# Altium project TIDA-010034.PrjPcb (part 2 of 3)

## Sheet TIDA-010034 PoE INPUT.SchDoc: PoE Input
size 431 x 279 mm; Date: Not shown in title block; ApprovedBy: Not shown in title block; CheckedBy: Not shown in title block; Author: Not shown in title block; CompanyName: Not shown in title block; DrawnBy: Surya Mishra; Engineer: Surya Mishra; Organization: Not shown in title block; Address1: Not shown in title block; Address2: Not shown in title block; Address3: Not shown in title block; Address4: Not shown in title block; DocumentNumber: 1; Revision: E1; SheetNumber: 2; SheetTotal: 9; PageSetup: Record=PageOptions¦CenterHorizontal=True¦CenterVertical=True¦PrintScale=1.00¦XCorrection=1.00¦YCorrection=1.00¦PrintKind=0¦BorderSize=5000000¦LeftOffset=0¦BottomOffset=0¦Orientation=2¦PaperLength=1000¦PaperWidth=1000¦Scale=100¦PaperSource=15¦PrintQuality=600¦MediaType=1¦DitherType=10¦PaperKind=Letter¦PrintScaleMode=1
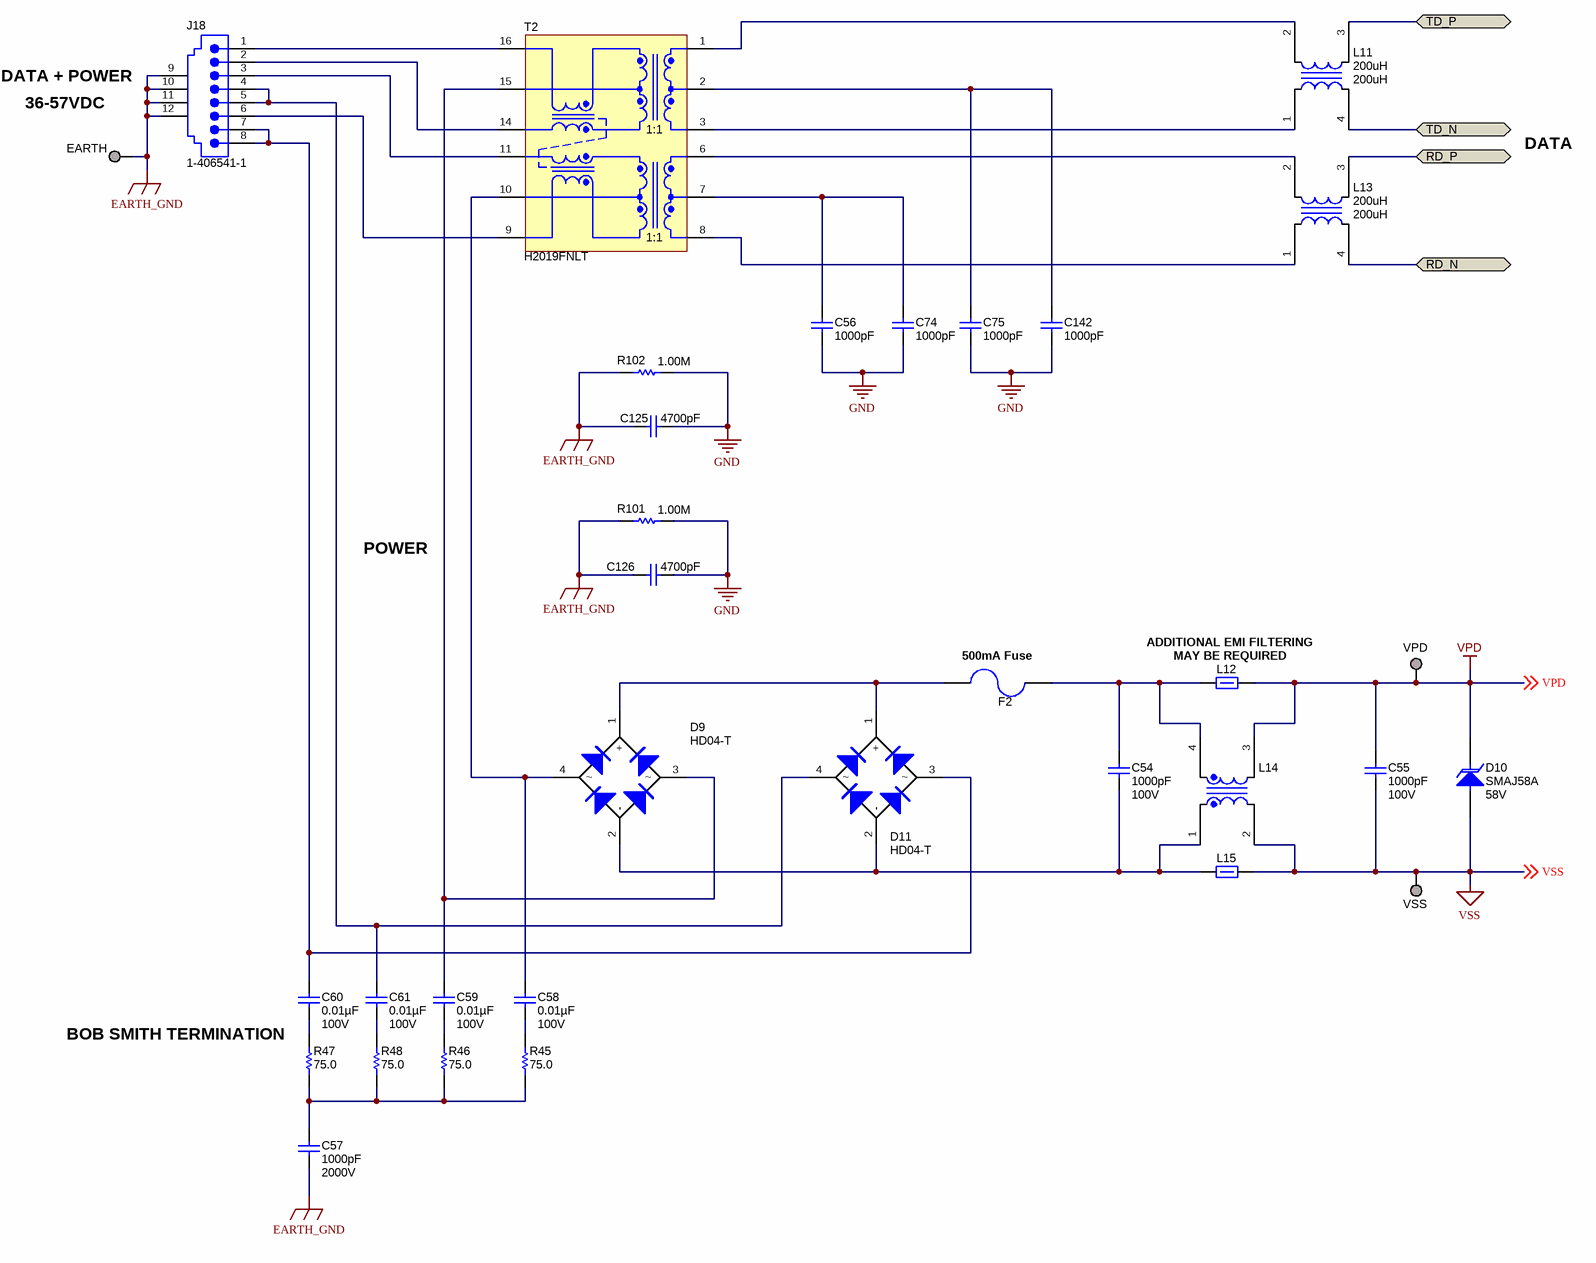
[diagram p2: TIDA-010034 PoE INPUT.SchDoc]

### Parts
C54  ValueDisplayed: 1000pF  Value2: 100V  [0603L]  (hidden comment: GRM188R72A102KA01D)
C55  ValueDisplayed: 1000pF  Value2: 100V  [0603L]  (hidden comment: GRM188R72A102KA01D)
C56  ValueDisplayed: 1000pF  [0603]  (hidden comment: GRM188R72A102KA01D)
C57  ValueDisplayed: 1000pF  Value2: 2000V  [1812]  (hidden comment: GR443QR73D102KW01L)
C58  ValueDisplayed: 0.01µF  Value2: 100V  [0603L]  (hidden comment: GRM188R72A103KA01D)
C59  ValueDisplayed: 0.01µF  Value2: 100V  [0603L]  (hidden comment: GRM188R72A103KA01D)
C60  ValueDisplayed: 0.01µF  Value2: 100V  [0603L]  (hidden comment: GRM188R72A103KA01D)
C61  ValueDisplayed: 0.01µF  Value2: 100V  [0603L]  (hidden comment: GRM188R72A103KA01D)
C74  ValueDisplayed: 1000pF  [0603]  (hidden comment: GRM188R72A102KA01D)
C75  ValueDisplayed: 1000pF  [0603]  (hidden comment: GRM188R72A102KA01D)
C125  ValueDisplayed: 4700pF  [1812_254]  (hidden comment: 1812GC472KAT1A)
C126  ValueDisplayed: 4700pF  [1812_254]  (hidden comment: 1812GC472KAT1A)
C142  ValueDisplayed: 1000pF  [0603]  (hidden comment: GRM188R72A102KA01D)
D9  HD04-T  [MiniDIP]
D10  SMAJ58A  value 58V  [SMA]
D11  HD04-T  [MiniDIP]
EARTH  TESTPOINT  [Keystone_5019]  (value not drawn)
F2  3413.0113.11  [Fuse_USF1206]  (value not drawn)
J18  1-406541-1  [TEC_1-406541-1]
L11  value 200uH  [TDK_ACT45L]  (hidden comment: ACT45L-201-2P-TL000)
L12  (no value)  [0603]
L13  value 200uH  [TDK_ACT45L]  (hidden comment: ACT45L-201-2P-TL000)
L14  DLW44SM242SK2L  [MuRata_DLW44SN]  (value not drawn)
L15  (no value)  [0603]
R45  value 75.0  [0603L]  (hidden comment: CRCW060375R0FKEA)
R46  value 75.0  [0603L]  (hidden comment: CRCW060375R0FKEA)
R47  value 75.0  [0603L]  (hidden comment: CRCW060375R0FKEA)
R48  value 75.0  [0603L]  (hidden comment: CRCW060375R0FKEA)
R101  ValueDisplayed: 1.00M  [2010]  (hidden comment: HVCB2010FKC1M00)
R102  ValueDisplayed: 1.00M  [2010]  (hidden comment: HVCB2010FKC1M00)
T2  H2019FNLT  [PULSE_H2019FNL]
VPD  TESTPOINT  [Keystone_5019]  (value not drawn)
VSS  TESTPOINT  [Keystone_5019]  (value not drawn)

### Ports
RD_N (bidir), RD_P (bidir), TD_N (bidir), TD_P (bidir)

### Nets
EARTH_GND: C57.1 C125.2 C126.2 EARTH.1 J18.9 J18.10 J18.11 J18.12 R101.1 R102.1
GND: C56.2 C74.2 C75.2 C125.1 C126.1 C142.2 R101.2 R102.2
VPD: C55.1 D10.1(K) L12.2 L14.3 VPD.1 ; off-sheet VPD
VSS: C55.2 D10.2(A) L14.2 L15.2 VSS.1 ; off-sheet VSS
RD_N: L13.4 ; port RD_N
RD_P: L13.3 ; port RD_P
TD_N: L11.4 ; port TD_N
TD_P: L11.3 ; port TD_P
NetC54_1: C54.1 F2.1 L12.1 L14.4
NetC54_2: C54.2 D9.2(-) D11.2(-) L14.1 L15.1
NetC56_1: C56.1 C74.1 T2.7(RCT)
NetC57_2: C57.2 R45.1 R46.1 R47.1 R48.1
NetC58_1: C58.1 D9.4 T2.10(RXCT)
NetC58_2: C58.2 R45.2
NetC59_1: C59.1 D9.3 T2.15(TXCT)
NetC59_2: C59.2 R46.2
NetC60_1: C60.1 D11.3 J18.7 J18.8
NetC60_2: C60.2 R47.2
NetC61_1: C61.1 D11.4 J18.4 J18.5
NetC61_2: C61.2 R48.2
NetC75_1: C75.1 C142.1 T2.2(TCT)
NetD9_1: D9.1(+) D11.1(+) F2.2
NetJ18_1: J18.1 T2.16(TX+)
NetJ18_2: J18.2 T2.14(TX-)
NetJ18_3: J18.3 T2.11(RX+)
NetJ18_6: J18.6 T2.9(RX-)
NetL11_1: L11.1 T2.3(TD-)
NetL11_2: L11.2 T2.1(TD+)
NetL13_1: L13.1 T2.8(RD-)
NetL13_2: L13.2 T2.6(RD+)

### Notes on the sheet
- DATA + POWER
- (near EARTH) 36-57VDC
- DATA
- POWER
- (near F2) 500mA Fuse
- (near L12) ADDITIONAL EMI FILTERING
- (near L12) MAY BE REQUIRED
- BOB SMITH TERMINATION

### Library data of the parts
C54 C55 = GRM188R72A102KA01D: CAP, CERM, 1000 pF, 100 V, +/- 10%, X7R, 0603; Manufacturer: MuRata; Polarized: N; CompType: Capacitor; Value: 1000pF; U/M: EA; Cap_F: 0.000000001; Tolerance_%: 10; Value1: Unknown; VDC_V: 100; TaMin_C: -55; TaMax_C: 125; Cap_Case: 0603; SizeArea_mm2: 1.28; SizeAreaWB_mm2: 4.68; SizeX_mm: 1.6; SizeY_mm: 0.8; SizeZ_mm: 1; AEC Category: Q200
C56 C74 C75 C142 = GRM188R72A102KA01D: CAP, CERM, 1000 pF, 100 V,+/- 10%, X7R, 0603; Manufacturer: MuRata; Polarized: N; CompType: Capacitor; Value: 1000pF; U/M: EA; Cap_F: 0.000000001; Tolerance_%: 10; VDC_V: 100; Value2: 100V; TaMin_C: -55; TaMax_C: 125; SizeArea_mm2: 1.28; SizeAreaWB_mm2: 4.68; SizeX_mm: 1.6; SizeY_mm: 0.8; SizeZ_mm: 1; AEC Category: Q200; Green_Lifecycle: Active; Green_REACh: Passed
C57 = GR443QR73D102KW01L: CAP, CERM, 1000 pF, 2000 V, +/- 10%, X7R, 1812; Manufacturer: MuRata; Polarized: N; CompType: Capacitor; Value: 1000pF; U/M: EA; Cap_F: 0.000000001; Tolerance_%: 10; Value1: Unknown; VDC_V: 2000; TaMin_C: -55; TaMax_C: 125; SizeArea_mm2: 14.4; SizeAreaWB_mm2: 23.1; SizeX_mm: 4.5; SizeY_mm: 3.2; SizeZ_mm: 1.35; AEC Category: Q200
C58-C61 = GRM188R72A103KA01D: CAP, CERM, 0.01 µF, 100 V, +/- 10%, X7R, 0603; Manufacturer: MuRata; Polarized: N; CompType: Capacitor; Value: 0.01uF; U/M: EA; Cap_F: 0.00000001; Tolerance_%: 10; Value1: Unknown; VDC_V: 100; TaMin_C: -55; TaMax_C: 125; Cap_Case: 0603; SizeArea_mm2: 1.28; SizeAreaWB_mm2: 4.68; SizeX_mm: 1.6; SizeY_mm: 0.8; SizeZ_mm: 1; AEC Category: Q200
C125 = CMP-0009295-2: CAP, CERM, 4700 pF, 2000 V, +/- 10%, X7R, 1812; Manufacturer: AVX; Polarized: N; Value: 4700pF; U/M: EA; Cap_F: 4.7nF; Value1: Unknown; VDC_V: 2kV; Value2: 2000V; TaMin_C: -55°C; TaMax_C: 125°C; Cap_Case: 1812; AEC Category: Q200; SizeArea_mm2: 14.4; SizeAreaWB_mm2: 23.1; SizeX_mm: 4.5; SizeY_mm: 3.2; SizeZ_mm: 2.54
C126 = CMP-0009295-2: CAP, CERM, 4700 pF, 2000 V, +/- 10%, X7R, 1812; Manufacturer: AVX; Polarized: N; CompType: Capacitor; Value: 4700pF; U/M: EA; Cap_F: 4.7nF; Value1: Unknown; VDC_V: 2kV; Value2: 2000V; TaMin_C: -55°C; TaMax_C: 125°C; Cap_Case: 1812; AEC Category: Q200; SizeArea_mm2: 14.4; SizeAreaWB_mm2: 23.1; SizeX_mm: 4.5; SizeY_mm: 3.2; SizeZ_mm: 2.54
D9 D11 = HD04-T: Diode, Switching-Bridge, 400V, 0.8A, MiniDIP; Manufacturer: Diodes Inc.; U/M: EA; Vf_V: 1; Value2: 1V; Io_A: 0.8; Vr_V: 400; TJmax_C: 150
D10 = SMAJ58A: Diode, TVS, Uni, 58 V, 400 W, SMA; Manufacturer: Diodes Inc.; U/M: EA; Power_W: 400; Vr_V: 58; Value1: 400W
EARTH VPD VSS = 5019: Test Point, Miniature, SMT; Manufacturer: Keystone; CompType: Test Point Loop; U/M: EA
F2 = CMP-0084010-1: Fuse, 0.5 A, 125VAC/VDC, SMD; Manufacturer: Schurter; Fuse Technology: Board Mount; VAC_V: 125V; SizeAreaWB_mm2: 10.92; Rtyp_Ohm: 0.315; SizeArea_mm2: 5.12; Fuse Speed: Fast; MeltingTyp: 0.01; Irating_A: 500mA; TaMax_C: 90°C; SizeZ_mm: 0.6; TaMin_C: -55°C; SizeY_mm: 1.6; SizeX_mm: 3.2
J18 = 1-406541-1: RJ-45, No LED, tab up, R/A, TH; Manufacturer: TE Connectivity; SymbolCreator: x0208326; CompType: Connector; ContactFinish: Gold
L11 L13 = CMP-0013189-2: Coupled inductor, 200 uH,  A, 4.5 ohm, SMD; Manufacturer: TDK; SizeAreaWB_mm2: 23.1; DCR_ohm: 4.5; SizeZ_mm: 2.95; SizeY_mm: 3.2; SizeArea_mm2: 14.4; Ind_H: 200µH
L12 L15 = CMP-0003355-2: Ferrite Bead, 330 ohm @ 100 MHz, 1.5 A, 0603; Manufacturer: MuRata; PartNumber: BLM18SG331TN1D; ZTyp@100MHz_Ohm: 330; SizeAreaWB_mm2: 4.68; DCR_ohm: 0.07; Value1: 0.07 ohm; Value: 330 ohm; Imax_A: 1.5A; SizeZ_mm: 1; SizeX_mm: 1.6; SizeY_mm: 0.8; SizeArea_mm2: 1.28
L14 = CMP-0084019-1: Coupled inductor, 0.105 ohm, SMD; Manufacturer: MuRata; SizeZ_mm: 1.5; SizeX_mm: 4.2; AEC Category: Q200; SizeArea_mm2: 17.64; AEC Qualified: N; SizeAreaWB_mm2: 27.04; DCR_ohm: 0.105
R45-R48 = CRCW060375R0FKEA: RES, 75.0 ohm, 1%, 0.1W, 0603; Manufacturer: Vishay-Dale; CompType: Resistor; Res_ohm: 75; Value_Code: 75R0; Tolerance_%: 1; Power_W: 0.1; TempCo: 100 ppm/C; EIA_Code: E96; U/M: EA
R101 R102 = CMP-0016535-2: RES, 1.00 M, 1%, 1 W, 2010; Manufacturer: Stackpole Electronics Inc; Power_W: 1W; TempCo: 50 ppm/C; Value_Code: 1M00; U/M: EA; Value: 1.00Meg; EIA_Code: E96; Res_ohm: 1M; SizeX_mm: 5; SizeY_mm: 2.5; SizeZ_mm: 1.66; SizeArea_mm2: 12.5; AEC Qualified: N; VDC_V: 2kV; AEC Category: Q200
T2 = H2019FNLT: Transformer, 350uH, SMT; Manufacturer: Pulse Engineering; SymbolCreator: x0208325; DCR_Ohm: 0.65; U/M: EA

## Sheet TIDA-010034 USB INPUT.SchDoc: USB Input for MSP430
size 431 x 279 mm; Date: Not shown in title block; ApprovedBy: Not shown in title block; CheckedBy: Not shown in title block; Author: Not shown in title block; CompanyName: Not shown in title block; DrawnBy: Surya Mishra; Engineer: Surya Mishra; Organization: Not shown in title block; Address1: Not shown in title block; Address2: Not shown in title block; Address3: Not shown in title block; Address4: Not shown in title block; DocumentNumber: 1; Revision: E1; SheetNumber: 6; SheetTotal: 9; PageSetup: Record=PageOptions¦CenterHorizontal=True¦CenterVertical=True¦PrintScale=1.00¦XCorrection=1.00¦YCorrection=1.00¦PrintKind=0¦BorderSize=5000000¦LeftOffset=0¦BottomOffset=0¦Orientation=2¦PaperLength=1000¦PaperWidth=1000¦Scale=100¦PaperSource=15¦PrintQuality=600¦MediaType=1¦DitherType=10¦PaperKind=Letter¦PrintScaleMode=1
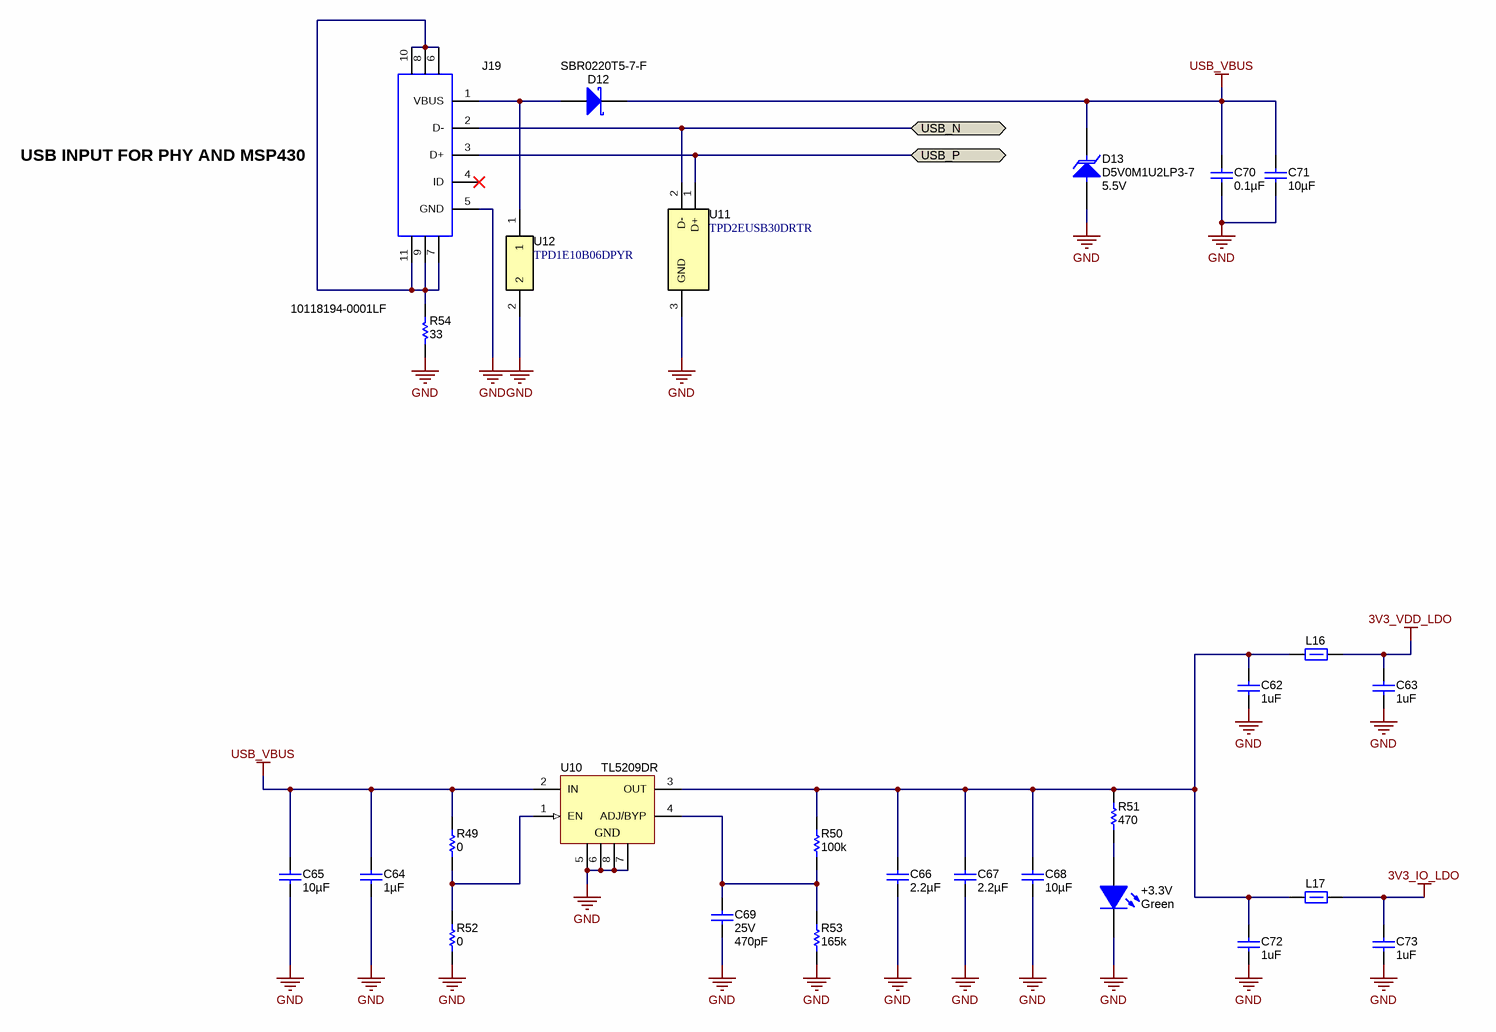
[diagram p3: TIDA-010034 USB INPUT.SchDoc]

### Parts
+3.3V  value Green  [QTLP630C_Green]  (hidden comment: QTLP630C4TR)
C62  ValueDisplayed: 1uF  [0402]  (hidden comment: GRM155R61A105KE15D)
C63  ValueDisplayed: 1uF  [0402]  (hidden comment: GRM155R61A105KE15D)
C64  ValueDisplayed: 1µF  [0603]  (hidden comment: GRM188R71C105KE15D)
C65  ValueDisplayed: 10µF  [0603]  (hidden comment: GRM188R61E106MA73D)
C66  ValueDisplayed: 2.2µF  [0603]  (hidden comment: GRM188Z71C225KE43)
C67  ValueDisplayed: 2.2µF  [0603]  (hidden comment: GRM188Z71C225KE43)
C68  ValueDisplayed: 10µF  [0603]  (hidden comment: GRM188R61E106MA73D)
C69  VDC_V: 25V  ValueDisplayed: 470pF  [0402]  (hidden comment: GRM1555C1E471JA01D)
C70  ValueDisplayed: 0.1µF  [0402]  (hidden comment: GCM155R71C104KA55D)
C71  ValueDisplayed: 10µF  [0603]  (hidden comment: GRM188R61E106MA73D)
C72  ValueDisplayed: 1uF  [0402]  (hidden comment: GRM155R61A105KE15D)
C73  ValueDisplayed: 1uF  [0402]  (hidden comment: GRM155R61A105KE15D)
D12  SBR0220T5-7-F  [SOD-523]
D13  D5V0M1U2LP3-7  value 5.5V  [X3-DFN0603-2]
J19  10118194-0001LF  [FCI_10118194-0001LF]
L16  BLM18AG102SN1D  [0603]  (value not drawn)
L17  BLM18AG102SN1D  [0603]  (value not drawn)
R49  ValueDisplayed: 0  [0402]  (hidden comment: CRCW04020000Z0ED)
R50  ValueDisplayed: 100k  [0402]  (hidden comment: CRCW0402100KDHEDP)
R51  ValueDisplayed: 470  [0402]  (hidden comment: CRCW0402470RJNED)
R52  ValueDisplayed: 0  [0402]  (hidden comment: CRCW04020000Z0ED)
R53  ValueDisplayed: 165k  [0402]  (hidden comment: CRCW0402165KFKED)
R54  ValueDisplayed: 33  [0402]  (hidden comment: CRCW040233R0JNED)
U10  TL5209DR  [D0008A_N]
U11  TPD2EUSB30DRTR  [DRT0003A]
U12  TPD1E10B06DPYR  [DPY0002A]

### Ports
USB_N (bidir), USB_P (bidir)

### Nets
3V3_IO_LDO: C73.1 L17.2
3V3_VDD_LDO: C63.1 L16.2
GND: +3.3V.2(K) C62.2 C63.2 C64.2 C65.2 C66.2 C67.2 C68.2 C69.2 C70.2 C71.2 C72.2 C73.2 D13.2(A) J19.5(GND) R52.1 R53.1 R54.2 U10.5(GND) U10.6(GND) U10.7(GND) U10.8(GND) U11.3(GND) U12.2
USB_VBUS: C64.1 C65.1 C70.1 C71.1 D12.1(K) D13.1(K) R49.2 U10.2(IN)
USB_N: J19.2(D-) U11.2(D-) ; port USB_N
USB_P: J19.3(D+) U11.1(D+) ; port USB_P
Net+3.3V_1: +3.3V.1(A) R51.1
NetC62_1: C62.1 C66.1 C67.1 C68.1 C72.1 L16.1 L17.1 R50.2 R51.2 U10.3(OUT)
NetC69_1: C69.1 R50.1 R53.2 U10.4(ADJ/BYP)
NetD12_2: D12.2(A) J19.1(VBUS) U12.1
NetJ19_6: J19.6 J19.7 J19.8 J19.9 J19.10 J19.11 R54.1
NetR49_1: R49.1 R52.2 U10.1(EN)

Not connected (* = marked no-connect by the designer): J19 4(ID)*

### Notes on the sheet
- USB INPUT FOR PHY AND MSP430

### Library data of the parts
+3.3V = CMP-0002917-1: LED, Green, SMD; Manufacturer: Everlight; Vf_V: 2.1V; Io_A: 20mA; Vr_V: 5V; Tjmax_C: 85°C; Value1: W; Angle: 140; U/M: EA
C62 C63 C72 C73 = CMP-0006563-2: CAP, CERM, 1 uF, 10 V, +/- 10%, X5R, 0402; Manufacturer: MuRata; Polarized: N; Value: 1uF; U/M: EA; Cap_F: 1µF; Value1: Unknown; VDC_V: 10V; TaMin_C: -55°C; TaMax_C: 85°C; AEC Category: Q200; SizeArea_mm2: 0.5; SizeAreaWB_mm2: 3; SizeX_mm: 1; SizeZ_mm: 0.6
C64 = GRM188R71C105KE15D: CAP, CERM, 1 µF, 16 V,+/- 10%, X7R, 0603; Manufacturer: MuRata; Polarized: N; CompType: Capacitor; Value: 1uF; U/M: EA; Cap_F: 0.000001; Tolerance_%: 10; VDC_V: 16; Value2: 16V; TaMin_C: -55; TaMax_C: 125; SizeArea_mm2: 1.28; SizeAreaWB_mm2: 4.68; SizeX_mm: 1.6; SizeY_mm: 0.8; SizeZ_mm: 1; AEC Category: Q200
C65 C68 C71 = GRM188R61E106MA73D: CAP, CERM, 10 µF, 25 V,+/- 20%, X5R, 0603; Manufacturer: MuRata; Polarized: N; CompType: Capacitor; Value: 10uF; U/M: EA; Cap_F: 0.00001; Tolerance_%: 20; VDC_V: 25; Value2: 25V; TaMin_C: -55; TaMax_C: 85; SizeArea_mm2: 1.28; SizeAreaWB_mm2: 4.68; SizeX_mm: 1.6; SizeY_mm: 0.8; SizeZ_mm: 1; AEC Category: Q200; Green_Lifecycle: Active; Green_REACh: Passed
C66 C67 = GRM188Z71C225KE43: CAP, CERM, 2.2 µF, 16 V,+/- 10%, X7R, 0603; Manufacturer: MuRata; Polarized: N; CompType: Capacitor; Value: 2.2uF; U/M: EA; Cap_F: 0.0000022; Tolerance_%: 10; VDC_V: 16; Value2: 16V; TaMin_C: -55; TaMax_C: 125; SizeArea_mm2: 1.28; SizeAreaWB_mm2: 4.68; SizeX_mm: 1.6; SizeY_mm: 0.8; SizeZ_mm: 1; AEC Category: Q200; Green_Lifecycle: Active; Green_REACh: Passed
C69 = CMP-0006389-2: CAP, CERM, 470 pF, 25 V, +/- 5%, C0G/NP0, 0402; Manufacturer: MuRata; TaMin_C: -55°C; Polarized: N; SizeAreaWB_mm2: 3; Value1: Unknown; U/M: EA; Value: 470pF; TaMax_C: 125°C; SizeZ_mm: 0.6; SizeX_mm: 1; SizeY_mm: 0.5; CompType: Capacitor; AEC Category: Q200
C70 = GCM155R71C104KA55D: CAP, CERM, 0.1 µF, 16 V,+/- 10%, X7R, 0402; Manufacturer: MuRata; Polarized: N; CompType: Capacitor; Value: 0.1uF; U/M: EA; Cap_F: 0.0000001; Tolerance_%: 10; VDC_V: 16; Value2: 16V; TaMin_C: -55; TaMax_C: 125; SizeArea_mm2: 0.5; SizeAreaWB_mm2: 3; SizeX_mm: 1; SizeZ_mm: 0.6; AEC Category: Q200; Green_Lifecycle: Active; Green_REACh: Passed
D12 = SBR0220T5-7-F: Diode, Schottky, 20 V, 0.2 A, SOD-523; Manufacturer: Diodes Inc.; U/M: EA; Vf_V: 0.47; Value: 20V; Value1: 0.2A; Value2: 0.47V; Io_A: 0.2; Vr_V: 20; SizeAreaWB_mm2: 5.13; SizeArea_mm2: 1.53; SizeX_mm: 1.7; SizeY_mm: 0.9; SizeZ_mm: 0.65; AEC Category: Q101; Green_Lifecycle: Not Set; Green_REACh: Incomplete
D13 = D5V0M1U2LP3-7: Diode, TVS, Uni, 5.5 V, 11 Vc, 2-XFDFN; Manufacturer: Diodes Inc.; U/M: EA; Power_W: 0.25; Vr_V: 5.5; Value1: 0.25W; RJA_CperW: 500; AEC Category: Q101; AEC Qualified: N
J19 = 10118194-0001LF: Receptacle, USB 2.0, Micro-USB Type B, R/A, SMT; Manufacturer: FCI; SymbolCreator: a0411947; Pitch_mm: 0.65; Gender: Female; Row_Count: 1; ContactFinish: Gold; Current_A: 1.8; Voltage_V: 100; Cert_UL: Y
L16 L17 = CMP-0003343-2: Ferrite Bead, 1000 ohm @ 100 MHz, 0.4 A, 0603; Manufacturer: MuRata; ZTyp@100MHz_Ohm: 1k; SizeAreaWB_mm2: 4.68; DCR_ohm: 5d; Value1: 0.5 ohm; Imax_A: 4dA; SizeZ_mm: 1; SizeX_mm: 1.6; SizeY_mm: 0.8; Value2: 0.4A; SizeArea_mm2: 1.28
R49 R52 = CRCW04020000Z0ED: RES, 0, 5%, 0.063 W, 0402; Manufacturer: Vishay-Dale; CompType: Resistor; Value: 0; Value_Code: 0000; Tolerance_%: 5; Power_W: 0.063; Value2: 0.063W; VDC_V: 50; TempCo: 200 ppm/C; SizeArea_mm2: 0.5; SizeX_mm: 1; SizeZ_mm: 0.6; EIA_Code: E24; U/M: EA; AEC Category: Q200; Green_Lifecycle: Active; Green_REACh: Passed
R50 = CMP-0026768-2: RES, 100 k, 0.5%, 0.063 W, AEC-Q200 Grade 0, 0402; Manufacturer: Vishay-Dale; Power_W: 63mW; TempCo: 50 ppm/C; Value: 100k; EIA_Code: E192; SizeX_mm: 1; SizeY_mm: 0.5; SizeZ_mm: 0.6; Value2: 0.063W; CompType: Resistor; AEC Qualified: Y; VDC_V: 50V; AEC Category: Q200; AEC Grade: 0
R51 = CMP-0026934-3: RES, 470, 5%, 0.063 W, AEC-Q200 Grade 0, 0402; Manufacturer: Vishay-Dale; Power_W: 63mW; TempCo: 200 ppm/C; Value_Code: 470R; Value: 470; EIA_Code: E24; SizeX_mm: 1; SizeY_mm: 0.5; SizeZ_mm: 0.6; Value2: 0.063W; CompType: Resistor; AEC Qualified: Y; VDC_V: 50V; AEC Category: Q200; AEC Grade: 0
R53 = CMP-0026036-3: RES, 165 k, 1%, 0.063 W, AEC-Q200 Grade 0, 0402; Manufacturer: Vishay-Dale; Power_W: 63mW; TempCo: 100 ppm/C; Value: 165k; EIA_Code: E96; SizeX_mm: 1; SizeY_mm: 0.5; SizeZ_mm: 0.6; Value2: 0.063W; AEC Qualified: Y; VDC_V: 50V; AEC Category: Q200; AEC Grade: 0
R54 = CMP-0026908-3: RES, 33, 5%, 0.063 W, AEC-Q200 Grade 0, 0402; Manufacturer: Vishay-Dale; Value: 33; Value_Code: 33R0; Power_W: 63mW; Value2: 0.063W; VDC_V: 50V; TempCo: 200 ppm/C; EIA_Code: E24; AEC Category: Q200; AEC Qualified: Y; AEC Grade: 0; SizeArea_mm2: 0.5; SizeX_mm: 1; SizeZ_mm: 0.6
U10 = CMP-0036447-1: Single Output Low Noise LDO, 500 mA, Adjustable 1.3 to 6.5 V Output, 2.5 to 16 V Input, 8-pin SOIC (D), -40 to 125 degC, Green (RoHS & no Sb/Br); Manufacturer: Texas Instruments; Iq(Typ)(mA): 8; Accuracy(%): 2; Vdo(Typ)(mV): 500; Iout(Max)(A): 0.5; Vin(Max)(V): 16; Vout Adj(Min)(V): 2.5; Vout Adj(Max)(V): 6.5; SubFamily: Single Channel LDO; Rating: Catalog
U11 = TPD2EUSB30DRTR: ESD Solution for Super-Speed (6 Gbps) USB 3.0 Interface, 2 Channels, -40 to +85 degC, 3-pin SOT (DRT), Green (Rohs & No Sb/Br); Manufacturer: Texas Instruments; Alternate PartNumber: Equivalent; 1394 / Firewire: TRUE; Breakdown Voltage(Min)(V): 9; Differential Capacitance(pF): 0.01; IEC 61000-4-2 Air-Gap(+/- kV): 8; IO Capacitance(Typ)(pF): 0.7; IO Leakage Current(nA): 10
U12 = TPD1E10B06DPYR: ESD in 0402 Package with 10 pF Capacitance and 6 V Breakdown, 1 Channel, -40 to +125 degC, 2-pin X2SON (DPY), Green (RoHS & no Sb/Br); Manufacturer: Texas Instruments; Alternate PartNumber: Equivalent; Breakdown Voltage(Min)(V): 6; Eco-Plan: TBD; IEC 61000-4-2 Air-Gap(+/- kV): 30; IO Capacitance(Typ)(pF): 10; SubFamily: ESD Solution

## Sheet TIDA-010034 Block Diagram.SchDoc: TIDA-010034 Power tree block diagram
size 431 x 279 mm; Date: Not shown in title block; ApprovedBy: Not shown in title block; CheckedBy: Not shown in title block; Author: Not shown in title block; CompanyName: Not shown in title block; DrawnBy: Surya Mishra; Engineer: Surya Mishra; Organization: Not shown in title block; Address1: Not shown in title block; Address2: Not shown in title block; Address3: Not shown in title block; Address4: Not shown in title block; DocumentNumber: 1; Revision: E1; SheetNumber: 1; SheetTotal: 9; PageSetup: Record=PageOptions¦CenterHorizontal=True¦CenterVertical=True¦PrintScale=1.00¦XCorrection=1.00¦YCorrection=1.00¦PrintKind=0¦BorderSize=5000000¦LeftOffset=0¦BottomOffset=0¦Orientation=2¦PaperLength=1000¦PaperWidth=1000¦Scale=100¦PaperSource=15¦PrintQuality=600¦MediaType=1¦DitherType=10¦PaperKind=Letter¦PrintScaleMode=1

## Sheet TIDA-010034 TPS23755 PD FRONT-END.SchDoc: TPS23755 based PD Front-end and 12V Adapter
size 431 x 279 mm; Date: Not shown in title block; ApprovedBy: Not shown in title block; CheckedBy: Not shown in title block; Author: Not shown in title block; CompanyName: Not shown in title block; DrawnBy: Surya Mishra; Engineer: Surya Mishra; Organization: Not shown in title block; Address1: Not shown in title block; Address2: Not shown in title block; Address3: Not shown in title block; Address4: Not shown in title block; DocumentNumber: 1; Revision: E1; SheetNumber: 3; SheetTotal: 9; PageSetup: Record=PageOptions¦CenterHorizontal=True¦CenterVertical=True¦PrintScale=1.00¦XCorrection=1.00¦YCorrection=1.00¦PrintKind=0¦BorderSize=5000000¦LeftOffset=0¦BottomOffset=0¦Orientation=2¦PaperLength=1000¦PaperWidth=1000¦Scale=100¦PaperSource=15¦PrintQuality=600¦MediaType=1¦DitherType=10¦PaperKind=Letter¦PrintScaleMode=1
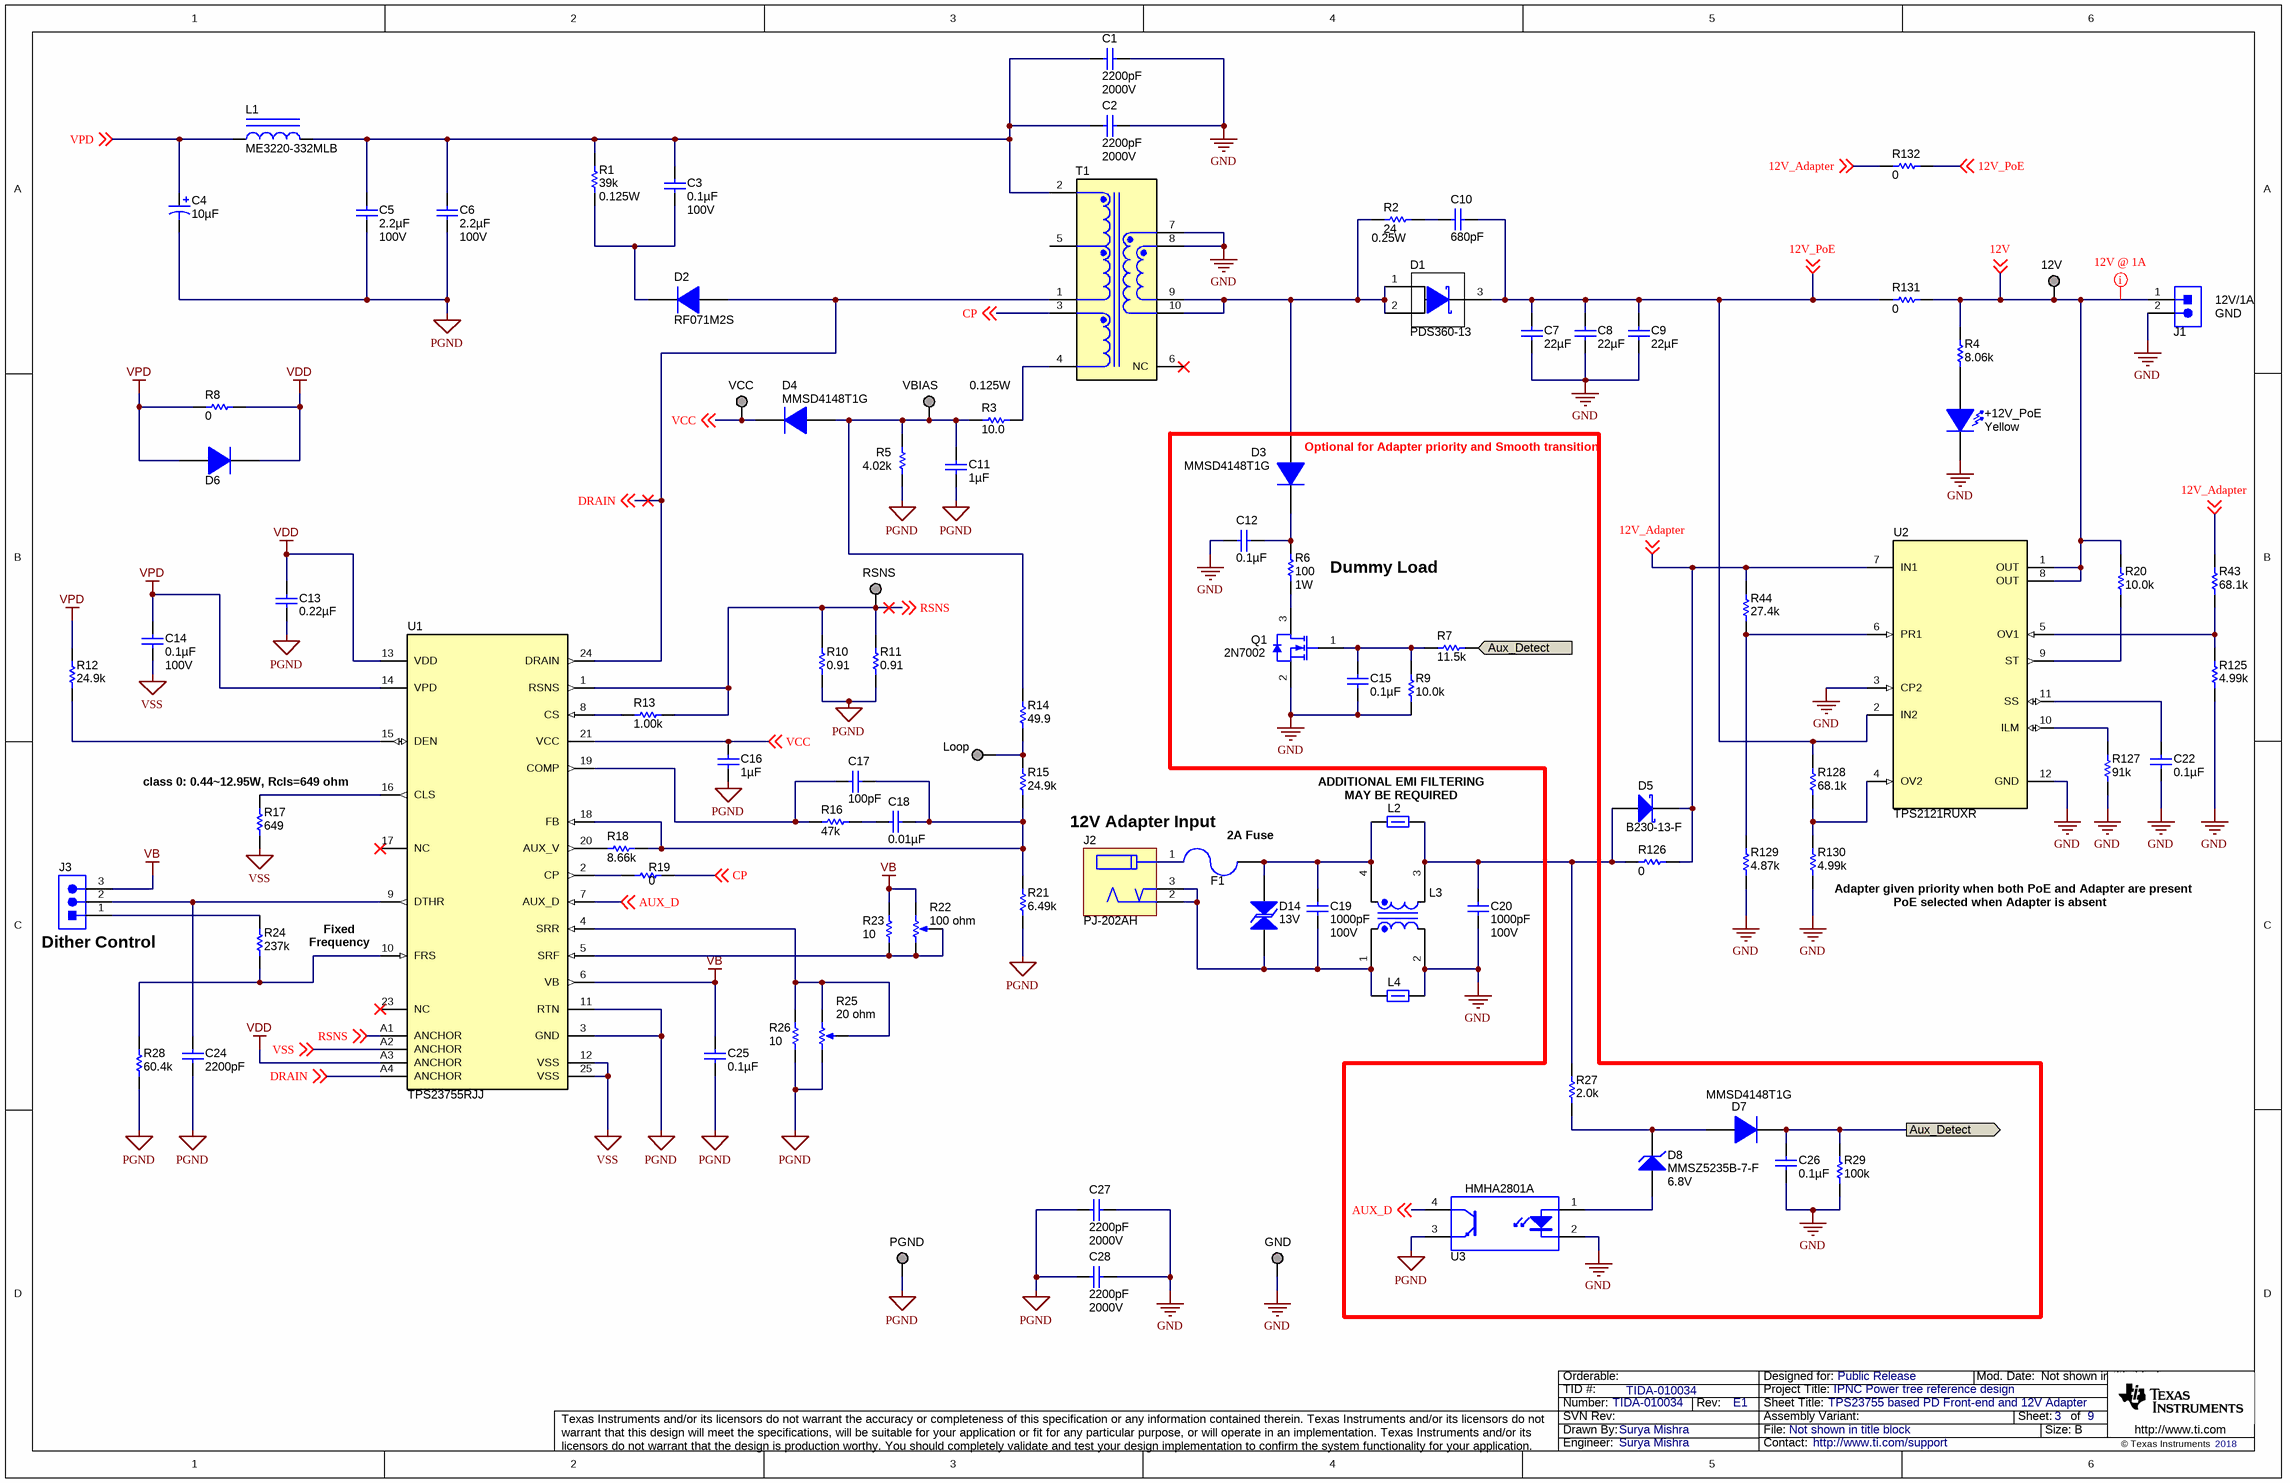
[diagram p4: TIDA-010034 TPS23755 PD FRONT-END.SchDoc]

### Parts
(Parts that share a designator on the sheet are numbered #1, #2 ... from top to bottom, then left to right.)
12V  TESTPOINT  [Keystone_5019]  (value not drawn)
+12V_PoE  value Yellow  [WL-SMCW_YELLOW]  (hidden comment: 150060YS75000)
C1  ValueDisplayed: 2200pF  Value2: 2000V  [1812]  (hidden comment: C4532X7R3D222K130KA)
C2  ValueDisplayed: 2200pF  Value2: 2000V  [1812]  (hidden comment: C4532X7R3D222K130KA)
C3  ValueDisplayed: 0.1µF  Value2: 100V  [0805_HV]  (hidden comment: C2012X7R2A104K125AA)
C4  ValueDisplayed: 10µF  [SM_RADIAL_E]  (hidden comment: EEE-2AA100UP)
C5  ValueDisplayed: 2.2µF  Value2: 100V  [1210_270L]  (hidden comment: GRM32ER72A225KA35L)
C6  ValueDisplayed: 2.2µF  Value2: 100V  [1210_270L]  (hidden comment: GRM32ER72A225KA35L)
C7  ValueDisplayed: 22µF  [1210_270]  (hidden comment: GRM32ER71E226KE15L)
C8  ValueDisplayed: 22µF  [1210_270]  (hidden comment: GRM32ER71E226KE15L)
C9  ValueDisplayed: 22µF  [1210_270]  (hidden comment: GRM32ER71E226KE15L)
C10  ValueDisplayed: 680pF  [0603]  (hidden comment: 06031C681KAT2A)
C11  ValueDisplayed: 1µF  [0805_HV]  (hidden comment: GRM21BR71H105KA12L)
C12  ValueDisplayed: 0.1µF  [0603]  (hidden comment: 06035C104KAT2A)
C13  ValueDisplayed: 0.22µF  [0805_HV]  (hidden comment: GRM21AR72A224KAC5L)
C14  ValueDisplayed: 0.1µF  Value2: 100V  [0805_HV]  (hidden comment: C2012X7R2A104K125AA)
C15  ValueDisplayed: 0.1µF  [0603]  (hidden comment: 06035C104KAT2A)
C16  ValueDisplayed: 1µF  [0805_HV]  (hidden comment: GRM21BR71H105KA12L)
C17  ValueDisplayed: 100pF  [0402L]  (hidden comment: 885012005061)
C18  ValueDisplayed: 0.01µF  [0603L]  (hidden comment: 06031C103MAT2A)
C19  ValueDisplayed: 1000pF  Value2: 100V  [0603]  (hidden comment: GRM188R72A102KA01D)
C20  ValueDisplayed: 1000pF  Value2: 100V  [0603]  (hidden comment: GRM188R72A102KA01D)
C22  ValueDisplayed: 0.1µF  [0603L]  (hidden comment: C1608X7R1E104K080AA)
C24  ValueDisplayed: 2200pF  [0603L]  (hidden comment: GRM188R71H222KA01D)
C25  ValueDisplayed: 0.1µF  [0603L]  (hidden comment: C1608X7R1E104K080AA)
C26  ValueDisplayed: 0.1µF  [0603L]  (hidden comment: 06035C104KAT2A)
C27  ValueDisplayed: 2200pF  Value2: 2000V  [1812]  (hidden comment: C4532X7R3D222K130KA)
C28  ValueDisplayed: 2200pF  Value2: 2000V  [1812]  (hidden comment: C4532X7R3D222K130KA)
D1  PDS360-13  [PowerDI5]
D2  RF071M2S  [SOD-123]
D3  MMSD4148T1G  [SOD-123]
D4  MMSD4148T1G  [SOD-123]
D5  B230-13-F  [SMB]
D6  MMSD4148T1G  [SOD-123]  (value not drawn)
D7  MMSD4148T1G  [SOD-123]
D8  MMSZ5235B-7-F  value 6.8V  [SOD-123]
D14  value 13V  [SMA]  (hidden comment: SMAJ13CA)
F1  3413.0112.24  [Fuse_USF1206]  (value not drawn)
GND#19  TESTPOINT  [Keystone_5019]  (value not drawn)
J1  ED555/2DS  [TERM_BLK_ED555-2DS]  (value not drawn)
J2  PJ-202AH  [CONN_CUI-PJ-202AH]
J3  TSW-103-07-G-S  [TSW-103-07-X-S]  (value not drawn)
L1  ME3220-332MLB  [ME3220]
L2  (no value)  [0603]
L3  DLW5BTM142TQ2L  [DLW5BT_TQ2]  (value not drawn)
L4  (no value)  [0603]
Loop  TESTPOINT  [Keystone_5019]  (value not drawn)
PGND  TESTPOINT  [Keystone_5019]  (value not drawn)
Q1  2N7002  [SOT-23]
R1  value 39k  Value2: 0.125W  [0805_HV]  (hidden comment: CRCW080539K0JNEA)
R2  ValueDisplayed: 24  Value2: 0.25W  [1206]  (hidden comment: CRCW120624R0JNEA)
R3  Value2: 0.125W  ValueDisplayed: 10.0  [0805L]  (hidden comment: RC0805FR-0710RL)
R4  ValueDisplayed: 8.06k  [0603]  (hidden comment: CRCW06038K06FKEA)
R5  ValueDisplayed: 4.02k  [0603L]  (hidden comment: CRCW06034K02FKEA)
R6  ValueDisplayed: 100  Value2: 1W  [2512]  (hidden comment: CRCW2512100RJNEG)
R7  ValueDisplayed: 11.5k  [0603]  (hidden comment: CRCW060311K5FKEA)
R8  ValueDisplayed: 0  [0603]  (hidden comment: MCT06030Z0000ZP500)
R9  ValueDisplayed: 10.0k  [0603]  (hidden comment: CRCW060310K0FKEA)
R10  ValueDisplayed: 0.91  [0805L]  (hidden comment: CRM0805-FX-R910ELF)
R11  ValueDisplayed: 0.91  [0805L]  (hidden comment: CRM0805-FX-R910ELF)
R12  ValueDisplayed: 24.9k  [0402L]  (hidden comment: CRCW040224K9FKED)
R13  ValueDisplayed: 1.00k  [0402L]  (hidden comment: ERJ-2RKF1001X)
R14  ValueDisplayed: 49.9  [0402L]  (hidden comment: RMCF0402FT49R9)
R15  ValueDisplayed: 24.9k  [0402L]  (hidden comment: CRCW040224K9FKED)
R16  ValueDisplayed: 47k  [0402L]  (hidden comment: CRCW040247K0JNED)
R17  ValueDisplayed: 649  [0603]  (hidden comment: CRCW0603649RFKEA)
R18  ValueDisplayed: 8.66k  [0402L]  (hidden comment: CRCW04028K66FKED)
R19  ValueDisplayed: 0  [0402L]  (hidden comment: RC0402JR-070RL)
R20  ValueDisplayed: 10.0k  [0603]  (hidden comment: CRCW060310K0FKEA)
R21  ValueDisplayed: 6.49k  [0402L]  (hidden comment: CRCW04026K49FKED)
R22  value 100 ohm  [Bourns_3314J-1]  (hidden comment: 3314J-1-101E)
R23  ValueDisplayed: 10  [0402L]  (hidden comment: CRCW040210R0JNED)
R24  ValueDisplayed: 237k  [0402L]  (hidden comment: CRCW0402237KFKED)
R25  value 20 ohm  [Bourns_3314J-1]  (hidden comment: 3314J-1-200E)
R26  ValueDisplayed: 10  [0402L]  (hidden comment: CRCW040210R0JNED)
R27  ValueDisplayed: 2.0k  [0603L]  (hidden comment: CRCW06032K00JNEA)
R28  ValueDisplayed: 60.4k  [0402L]  (hidden comment: CRCW040260K4FKED)
R29  ValueDisplayed: 100k  [0603L]  (hidden comment: RC0603FR-07100KL)
R43  ValueDisplayed: 68.1k  [0402]  (hidden comment: CRCW040268K1FKED)
R44  ValueDisplayed: 27.4k  [0402]  (hidden comment: CRCW040227K4FKED)
R125  ValueDisplayed: 4.99k  [0402]  (hidden comment: CRCW04024K99FKED)
R126  ValueDisplayed: 0  [1206]  (hidden comment: CRCW12060000Z0EA)
R127  ValueDisplayed: 91k  [0603]  (hidden comment: CRCW060391K0JNEA)
R128  ValueDisplayed: 68.1k  [0402]  (hidden comment: CRCW040268K1FKED)
R129  ValueDisplayed: 4.87k  [0402]  (hidden comment: CRCW04024K87FKED)
R130  ValueDisplayed: 4.99k  [0402]  (hidden comment: CRCW04024K99FKED)
R131  ValueDisplayed: 0  [1206]  (hidden comment: CRCW12060000Z0EA)
R132  ValueDisplayed: 0  [1206]  (hidden comment: CRCW12060000Z0EA)
RSNS  TESTPOINT  [Keystone_5019]  (value not drawn)
T1  LDT0950-50  [Linkcom_LDT0937-50]  (value not drawn)
U1  TPS23755RJJ  [RJJ0023B]
U2  TPS2121RUXR  [RUX0012A]
U3  HMHA2801A  [MFP04A]
VBIAS  TESTPOINT  [Keystone_5019]  (value not drawn)
VCC  TESTPOINT  [Keystone_5019]  (value not drawn)

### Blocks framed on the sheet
Dummy Load: C12 C15 C26 D3 D7 D8 Q1 R6 R7 R9 R27 R29 U3

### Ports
Aux_Detect (in), Aux_Detect (out)

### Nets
GND: +12V_PoE.1(K) C1.2 C2.2 C7.2 C8.2 C9.2 C12.1 C15.2 C20.2 C22.2 C26.2 C27.2 C28.2 GND#19.1 J1.2 L3.2 L4.2 Q1.2(S) R9.1 R29.1 R125.1 R127.1 R129.1 R130.1 T1.7 T1.8 U2.3(CP2) U2.12(GND) U3.2(K)
PGND: C4.2(-) C5.2 C6.2 C11.2 C13.2 C16.2 C24.2 C25.2 C27.1 C28.1 PGND.1 R5.1 R10.1 R11.1 R21.1 R25.1(CCW) R26.2 R28.1 U1.3(GND) U1.11(RTN) U3.3(E)
VB: C25.1 J3.3 R22.3(CW) R23.1 U1.6(VB)
VDD: C13.1 D6.1(K) R8.1 U1.13(VDD) U1.A3(ANCHOR)
VPD: C4.1(+) C14.1 D6.2(A) L1.1 R8.2 R12.1 U1.14(VPD) ; off-sheet VPD
VSS: C14.2 R17.1 U1.12(VSS) U1.25(VSS) U1.A2(ANCHOR) ; off-sheet VSS
12V: 12V.1 J1.1 R4.2 R20.2 R131.2 U2.1(OUT) U2.8(OUT) ; off-sheet 12V
12V_Adapter: D5.1(K) R43.2 R44.2 R126.2 R132.1 U2.7(IN1) ; off-sheet 12V_Adapter
12V_PoE: C7.1 C8.1 C9.1 C10.1 D1.3(K) R128.2 R131.1 R132.2 U2.2(IN2) ; off-sheet 12V_PoE
AUX_D: U1.7(AUX_D) U3.4(C) ; off-sheet AUX_D
Aux_Detect: C26.1 D7.1(K) R7.2 R29.2 ; port Aux_Detect
CP: R19.2 T1.3 ; off-sheet CP
DRAIN: D2.2(A) T1.1 U1.24(DRAIN) U1.A4(ANCHOR) ; off-sheet DRAIN
RSNS: R10.2 R11.2 R13.2 RSNS.1 U1.1(RSNS) U1.A1(ANCHOR) ; off-sheet RSNS
VCC: C16.1 D4.1(K) U1.21(VCC) VCC.1 ; off-sheet VCC
Net+12V_PoE_2: +12V_PoE.2(A) R4.1
NetC1_1: C1.1 C2.1 C3.1 C5.1 C6.1 L1.2 R1.2 T1.2
NetC3_2: C3.2 D2.1(K) R1.1
NetC10_2: C10.2 R2.2
NetC11_1: C11.1 D4.2(A) R3.1 R5.2 R14.2 VBIAS.1
NetC12_2: C12.2 D3.1(K) R6.2
NetC15_1: C15.1 Q1.1(G) R7.1 R9.2
NetC17_1: C17.1 R16.2 U1.19(COMP)
NetC17_2: C17.2 C18.2 R15.1 R18.2 R21.2 U1.18(FB)
NetC18_1: C18.1 R16.1
NetC19_1: C19.1 D14.2 F1.1 L2.1 L3.4
NetC19_2: C19.2 D14.1 J2.2 J2.3 L3.1 L4.1
NetC20_1: C20.1 D5.2(A) L2.2 L3.3 R27.2 R126.1
NetC22_1: C22.1 U2.11(SS)
NetC24_1: C24.1 J3.2 U1.9(DTHR)
NetD1_1: D1.1(A) D1.2(A) D3.2(A) R2.1 T1.9 T1.10
NetD7_2: D7.2(A) D8.1(K) R27.1
NetD8_2: D8.2(A) U3.1(A)
NetF1_2: F1.2 J2.1
NetJ3_1: J3.1 R24.2
NetLoop_1: Loop.1 R14.1 R15.2
NetQ1_3: Q1.3(D) R6.1
NetR3_2: R3.2 T1.4
NetR12_2: R12.2 U1.15(DEN)
NetR13_1: R13.1 U1.8(CS)
NetR17_2: R17.2 U1.16(CLS)
NetR18_1: R18.1 U1.20(AUX_V)
NetR19_1: R19.1 U1.2(CP)
NetR20_1: R20.1 U2.9(ST)
NetR22_1: R22.1(CCW) R22.2(WIPER) R23.2 U1.5(SRF)
NetR24_1: R24.1 R28.2 U1.10(FRS)
NetR25_2: R25.2(WIPER) R25.3(CW) R26.1 U1.4(SRR)
NetR43_1: R43.1 R125.2 U2.5(OV1)
NetR44_1: R44.1 R129.2 U2.6(PR1)
NetR127_2: R127.2 U2.10(ILM)
NetR128_1: R128.1 R130.2 U2.4(OV2)

Not connected (* = marked no-connect by the designer): T1 5 6(NC)*; U1 17(NC)* 23(NC)*

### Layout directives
net class Undefined: 12V

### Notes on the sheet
- (near J1) 12V/1A
- (near J1) GND
- (near D3) Optional for Adapter priority and Smooth transition
- (near R17) class 0: 0.44
  2.95W, Rcls=649 ohm
- 12V Adapter Input
- (near F1) 2A Fuse
- (near L2) ADDITIONAL EMI FILTERING
- (near L2) MAY BE REQUIRED
- PoE selected when Adapter is absent
- (near R130) Adapter given priority when both PoE and Adapter are present
- (near J3) Dither Control
- Frequency
- Fixed

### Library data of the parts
12V GND#19 Loop PGND RSNS VBIAS VCC = 5019: as EARTH on sheet TIDA-010034 PoE INPUT
+12V_PoE = 150060YS75000: LED, Yellow, SMD; Manufacturer: Wurth Elektronik; Vf_V: 2; Value2: 2V; Io_A: 0.02; Value1: W; U/M: EA
C1 C2 C27 C28 = C4532X7R3D222K130KA: CAP, CERM, 2200 pF, 2000 V, +/- 10%, X7R, 1812; Manufacturer: TDK; Polarized: N; CompType: Capacitor; Value: 2200pF; U/M: EA; Cap_F: 0.0000000022; Tolerance_%: 10; Value1: Unknown; VDC_V: 2000; TaMin_C: -55; TaMax_C: 125; SizeArea_mm2: 14.4; SizeAreaWB_mm2: 23.1; SizeX_mm: 4.5; SizeY_mm: 3.2; SizeZ_mm: 1.35; AEC Category: Q200
C3 C14 = C2012X7R2A104K125AA: CAP, CERM, 0.1 µF, 100 V, +/- 10%, X7R, 0805; Manufacturer: TDK; Polarized: N; CompType: Capacitor; Value: 0.1uF; U/M: EA; Cap_F: 0.0000001; Tolerance_%: 10; ESR_ohm: 0.020726; Value1: 0.020726 ohm; VDC_V: 100; IRMS_A: 1.456; TaMin_C: -55; TaMax_C: 125; Cap_Case: 0805; SizeArea_mm2: 2.5; SizeAreaWB_mm2: 6.75; SizeX_mm: 2; SizeY_mm: 1.25; SizeZ_mm: 1.45; AEC Category: Q200
C4 = EEE-2AA100UP: CAP, AL, 10 µF, 100 V, +/- 20%, AEC-Q200 Grade 3, SMD; Manufacturer: Panasonic; Polarized: Y; CompType: Capacitor; Value: 10uF; U/M: EA; Cap_F: 0.00001; Tolerance_%: 20; Value1: Unknown; VDC_V: 100; Value2: 100V; IRMS_A: 0.05; TaMin_C: -40; TaMax_C: 85; Cap_Case: 8.0x6.0mm; SizeAreaWB_mm2: 118.45; SizeArea_mm2: 78.85; SizeX_mm: 9.5; SizeY_mm: 8.3; SizeZ_mm: 6.2; AEC Category: Q200; AEC Grade: 3
C5 C6 = GRM32ER72A225KA35L: CAP, CERM, 2.2 µF, 100 V, +/- 10%, X7R, 1210; Manufacturer: MuRata; Polarized: N; CompType: Capacitor; Value: 2.2uF; U/M: EA; Cap_F: 0.0000022; Tolerance_%: 10; ESR_ohm: 0.007; Value1: 0.007 ohm; VDC_V: 100; IRMS_A: 4.4; TaMin_C: -55; TaMax_C: 125; Cap_Case: 1210; SizeArea_mm2: 8; SizeAreaWB_mm2: 14.7; SizeX_mm: 3.2; SizeY_mm: 2.5; SizeZ_mm: 2.7; AEC Category: Q200
C7-C9 = GRM32ER71E226KE15L: CAP, CERM, 22 µF, 25 V,+/- 10%, X7R, 1210; Manufacturer: MuRata; Polarized: N; CompType: Capacitor; Value: 22uF; U/M: EA; Cap_F: 0.000022; Tolerance_%: 10; ESR_ohm: 0.002334; Value1: 0.002334 ohm; VDC_V: 25; Value2: 25V; IRMS_A: 3.832999; TaMin_C: -55; TaMax_C: 125; Cap_Case: 1210; SizeArea_mm2: 8; SizeAreaWB_mm2: 14.7; SizeX_mm: 3.2; SizeY_mm: 2.5; SizeZ_mm: 2.7; AEC Category: Q200; Green_Lifecycle: Active; Green_REACh: Passed
C10 = 06031C681KAT2A: CAP, CERM, 680 pF, 100 V, +/- 10%, X7R, 0603; Manufacturer: AVX; Polarized: N; CompType: Capacitor; Value: 680pF; U/M: EA; Cap_F: 0.00000000068; Tolerance_%: 10; ESR_ohm: 0.332; Value1: 0.332 ohm; VDC_V: 100; Value2: 100V; TaMin_C: -55; TaMax_C: 125; SizeArea_mm2: 1.28; SizeAreaWB_mm2: 4.68; SizeX_mm: 1.6; SizeY_mm: 0.8; SizeZ_mm: 1; AEC Category: Q200
C11 C16 = GRM21BR71H105KA12L: CAP, CERM, 1 µF, 50 V,+/- 10%, X7R, 0805; Manufacturer: MuRata; Polarized: N; CompType: Capacitor; Value: 1uF; U/M: EA; Cap_F: 0.000001; Tolerance_%: 10; VDC_V: 50; Value2: 50V; TaMin_C: -55; TaMax_C: 125; Cap_Case: 0805; SizeArea_mm2: 2.5; SizeAreaWB_mm2: 6.75; SizeX_mm: 2; SizeY_mm: 1.25; SizeZ_mm: 1.45; AEC Category: Q200; Green_Lifecycle: Active; Green_REACh: Passed
C12 C15 = 06035C104KAT2A: CAP, CERM, 0.1 µF, 50 V,+/- 10%, X7R, 0603; Manufacturer: AVX; Polarized: N; CompType: Capacitor; Value: 0.1uF; U/M: EA; Cap_F: 0.0000001; Tolerance_%: 10; VDC_V: 50; Value2: 50V; TaMin_C: -55; TaMax_C: 125; SizeArea_mm2: 1.28; SizeAreaWB_mm2: 4.68; SizeX_mm: 1.6; SizeY_mm: 0.8; SizeZ_mm: 1; AEC Category: Q200; Green_Lifecycle: Active; Green_REACh: Passed
C13 = GRM21AR72A224KAC5L: CAP, CERM, 0.22 µF, 100 V,+/- 10%, X7R, 0805; Manufacturer: MuRata; Polarized: N; CompType: Capacitor; Value: 0.22uF; U/M: EA; Cap_F: 0.00000022; Tolerance_%: 10; VDC_V: 100; Value2: 100V; TaMin_C: -55; TaMax_C: 125; Cap_Case: 0805; SizeArea_mm2: 2.5; SizeAreaWB_mm2: 6.75; SizeX_mm: 2; SizeY_mm: 1.25; SizeZ_mm: 1.45; AEC Category: Q200
C17 = 885012005061: CAP, CERM, 100 pF, 50 V,+/- 5%, C0G/NP0, 0402; Manufacturer: Wurth Elektronik; Polarized: N; CompType: Capacitor; Value: 100pF; U/M: EA; Cap_F: 0.0000000001; Tolerance_%: 5; VDC_V: 50; Value2: 50V; TaMin_C: -55; TaMax_C: 125; Cap_Case: 0402; SizeArea_mm2: 0.5; SizeAreaWB_mm2: 3; SizeX_mm: 1; SizeZ_mm: 0.6; AEC Category: Q200; Green_Lifecycle: Not Set; Green_REACh: Incomplete
C18 = 06031C103MAT2A: CAP, CERM, 0.01 µF, 100 V,+/- 20%, X7R, 0603; Manufacturer: AVX; Polarized: N; CompType: Capacitor; Value: 0.01uF; U/M: EA; Cap_F: 0.00000001; Tolerance_%: 20; ESR_ohm: 0.098; Value1: 0.098 ohm; VDC_V: 100; Value2: 100V; TaMin_C: -55; TaMax_C: 125; Cap_Case: 0603; SizeArea_mm2: 1.28; SizeAreaWB_mm2: 4.68; SizeX_mm: 1.6; SizeY_mm: 0.8; SizeZ_mm: 1; AEC Category: Q200; Green_Lifecycle: Active; Green_REACh: Passed
C19 C20 = GRM188R72A102KA01D: CAP, CERM, 1000 pF, 100 V, +/- 10%, X7R, 0603; Manufacturer: MuRata; Polarized: N; CompType: Capacitor; Value: 1000pF; U/M: EA; Cap_F: 0.000000001; Tolerance_%: 10; Value1: Unknown; VDC_V: 100; TaMin_C: -55; TaMax_C: 125; SizeArea_mm2: 1.28; SizeAreaWB_mm2: 4.68; SizeX_mm: 1.6; SizeY_mm: 0.8; SizeZ_mm: 1; AEC Category: Q200
C22 C25 = C1608X7R1E104K080AA: CAP, CERM, 0.1 µF, 25 V, +/- 10%, X7R, 0603; Manufacturer: TDK; Polarized: N; CompType: Capacitor; Value: 0.1uF; U/M: EA; Cap_F: 0.0000001; Tolerance_%: 10; Value1: Unknown; VDC_V: 25; Value2: 25V; TaMin_C: -55; TaMax_C: 125; Cap_Case: 0603; SizeArea_mm2: 1.28; SizeAreaWB_mm2: 4.68; SizeX_mm: 1.6; SizeY_mm: 0.8; SizeZ_mm: 1; AEC Category: Q200
C24 = GRM188R71H222KA01D: CAP, CERM, 2200 pF, 50 V, +/- 10%, X7R, 0603; Manufacturer: MuRata; Polarized: N; CompType: Capacitor; Value: 2200pF; U/M: EA; Cap_F: 0.0000000022; Tolerance_%: 10; Value1: Unknown; VDC_V: 50; Value2: 50V; TaMin_C: -55; TaMax_C: 125; Cap_Case: 0603; SizeArea_mm2: 1.28; SizeAreaWB_mm2: 4.68; SizeX_mm: 1.6; SizeY_mm: 0.8; SizeZ_mm: 1; AEC Category: Q200
C26 = 06035C104KAT2A: CAP, CERM, 0.1 µF, 50 V,+/- 10%, X7R, 0603; Manufacturer: AVX; Polarized: N; CompType: Capacitor; Value: 0.1uF; U/M: EA; Cap_F: 0.0000001; Tolerance_%: 10; VDC_V: 50; Value2: 50V; TaMin_C: -55; TaMax_C: 125; Cap_Case: 0603; SizeArea_mm2: 1.28; SizeAreaWB_mm2: 4.68; SizeX_mm: 1.6; SizeY_mm: 0.8; SizeZ_mm: 1; AEC Category: Q200; Green_Lifecycle: Active; Green_REACh: Passed
D1 = PDS360-13: Diode, Schottky, 60 V, 3 A, PowerDI5; Manufacturer: Diodes Inc.; U/M: EA; Vf_V: 0.62; Value: 60V; Value1: 3A; Value2: 0.62V; Io_A: 3; Vr_V: 60; TJmax_C: 150; SizeAreaWB_mm2: 49.56; SizeArea_mm2: 24.96; SizeX_mm: 6.4; SizeY_mm: 3.9; SizeZ_mm: 1.05; AEC Category: Q101
D2 = RF071M2S: Diode, Ultrafast, 200 V, 1 A, SOD-123; Manufacturer: Rohm; Value: 200V; U/M: EA; Vf_V: 0.85; Value1: 1A; Value2: 0.85V; Io_A: 1; Vr_V: 200; TJmax_C: 150; SizeAreaWB_mm2: 13.095; SizeArea_mm2: 6.545; SizeX_mm: 3.85; SizeY_mm: 1.7; SizeZ_mm: 1.35; AEC Category: Q101; Green_Lifecycle: Not Set; Green_REACh: Incomplete
D3 D4 D6 D7 = MMSD4148T1G: Diode, Switching, 100V, 0.2A, SOD-123; Manufacturer: ON Semiconductor; U/M: EA; Vf_V: 1; Value2: 1V; Io_A: 0.2; Vr_V: 100; TJmax_C: 150
D5 = B230-13-F: Diode, Schottky, 30 V, 2 A, SMB; Manufacturer: Diodes Inc.; U/M: EA; Vf_V: 0.5; Value: 30V; Value1: 2A; Value2: 0.5V; Io_A: 2; Vr_V: 30; TJmax_C: 150; RJC_CperW: 20; SizeAreaWB_mm2: 44.156; SizeArea_mm2: 21.336; SizeX_mm: 5.6; SizeY_mm: 3.81; SizeZ_mm: 2.6; AEC Category: Q101
D8 = MMSZ5235B-7-F: Diode, Zener, 6.8 V, 500 mW, SOD-123; Manufacturer: Diodes Inc.; SymbolCreator: a0412235; U/M: EA; Power_W: 0.5; Vz_V: 6.8; Value1: 0.5W; RJA_CperW: 350; SizeAreaWB_mm2: 13.095; SizeArea_mm2: 6.545; SizeX_mm: 3.85; SizeY_mm: 1.7; SizeZ_mm: 1.35; AEC Category: Q101; Green_Lifecycle: Active; Green_REACh: Passed
D14 = SMAJ13CA: Diode, TVS, Bi, 13 V, SMA; Manufacturer: Littelfuse; U/M: EA; Power_W: 3.3; Vr_V: 13; Value1: 3.3W; RJA_CperW: 120; SizeAreaWB_mm2: 37.3428; SizeArea_mm2: 16.3228; SizeX_mm: 5.59; SizeY_mm: 2.92; SizeZ_mm: 2.87; AEC Category: Q101
F1 = CMP-0084010-1: Fuse, 2 A, 125VAC/VDC, SMD; PartNumber: 3413.0119.11; Manufacturer: Schurter; Fuse Technology: Board Mount; VAC_V: 125V; SizeAreaWB_mm2: 10.92; Rtyp_Ohm: 0.315; SizeArea_mm2: 5.12; Fuse Speed: Fast; MeltingTyp: 0.01; Irating_A: 2A; TaMax_C: 90°C; SizeZ_mm: 0.6; TaMin_C: -55°C; SizeY_mm: 1.6; SizeX_mm: 3.2
J1 = ED555/2DS: Terminal Block, 6A, 3.5mm Pitch, 2-Pos, TH; Manufacturer: On-Shore Technology; SymbolCreator: a0412235; CompType: Connector; U/M: EA
J2 = PJ-202AH: Connector, DC Jack 2.1X5.5 mm, TH; Manufacturer: CUI Inc.; SymbolCreator: a0799628; CompType: Power Jack; Green_Lifecycle: Not Set; Green_REACh: Incomplete
J3 = TSW-103-07-G-S: Header, 100mil, 3x1, Gold, TH; Manufacturer: Samtec; SymbolCreator: a0799628; Pitch_mm: 2.54; Gender: Male; Shrouded: N; Row_Count: 1; Current_A: 6.3; Voltage_V: 550; Cert_CSA: Y; Green_Lifecycle: Active; Green_REACh: Passed
L1 = ME3220-332MLB: Inductor, Drum Core, Ferrite, 3.3 µH, 1.6 A, 0.14 ohm, SMD; Manufacturer: Coilcraft; Value: 3.3uH; ValueDisplayed: 3.3µH; Ind_H: 3.3E-6; Imax_A: 1.6; Irms: 1.6A @ 40C rise; Isat: 1.7A @ 30% inductance drop; DCR_ohm: 0.14; Value2: 1.6A; SizeAreaWB_mm2: 15.96; SizeArea_mm2: 8.96; SizeX_mm: 3.2; SizeY_mm: 2.8; SizeZ_mm: 2; AEC Category: Q200
L2 L4 = CMP-0003353-2: Ferrite Bead, 220 ohm @ 100 MHz, 2.5 A, 0603; Manufacturer: MuRata; PartNumber: BLM18SG221TN1D; ZTyp@100MHz_Ohm: 220; SizeAreaWB_mm2: 4.68; DCR_ohm: 0.04; Value1: 0.04 ohm; Value: 220 ohm; Imax_A: 2.5A; SizeZ_mm: 1; SizeX_mm: 1.6; SizeY_mm: 0.8; SizeArea_mm2: 1.28
L3 = CMP-0084018-1: Coupled inductor, 0.056 ohm, SMD; Manufacturer: MuRata; PartNumber: DLW5BTM102TQ2; AEC Category: Q200; AEC Qualified: N; DCR_ohm: 0.056
Q1 = 2N7002: MOSFET, N-CH, 60 V, 115 A, SOT-23; Manufacturer: Fairchild Semiconductor; Alternate Manufacturer: None; U/M: EA; ChType: N; Value: 60V; VdsMax_V: 60; Value1: ? ohm; Value2: ? nC; Vgs_V: 20; IdsMax_A: 115; SizeAreaWB_mm2: 14; SizeArea_mm2: 7.5; SizeX_mm: 2.5; SizeY_mm: 3; SizeZ_mm: 1.1; AEC Category: Q101
R1 = CRCW080539K0JNEA: RES, 39k ohm, 5%, 0.125W, 0805; Manufacturer: Vishay-Dale; CompType: Resistor; Res_ohm: 39000; Value_Code: 39k0; Tolerance_%: 5; Power_W: 0.125; VDC_V: 150; TempCo: 200 ppm/C; EIA_Code: E24; U/M: EA
R2 = CRCW120624R0JNEA: RES, 24, 5%, 0.25 W, 1206; Manufacturer: Vishay-Dale; CompType: Resistor; Value: 24; Value_Code: 24R0; Tolerance_%: 5; Power_W: 0.25; VDC_V: 200; TempCo: 200 ppm/C; SizeArea_mm2: 5.12; SizeX_mm: 3.2; SizeY_mm: 1.6; SizeZ_mm: 1.35; EIA_Code: E24; U/M: EA; AEC Category: Q200
R3 = RC0805FR-0710RL: RES, 10.0, 1%, 0.125 W, 0805; Manufacturer: Yageo America; CompType: Resistor; Value: 10.0; Res_ohm: 10; Value_Code: 10R0; Tolerance_%: 1; Power_W: 0.125; VDC_V: 150; TempCo: 200 ppm/C; EIA_Code: E96; U/M: EA; SizeArea_mm2: 2.5; SizeX_mm: 2; SizeY_mm: 1.25; SizeZ_mm: 1.45; AEC Category: Q200; Green_Lifecycle: Active; Green_REACh: Passed
R4 = CRCW06038K06FKEA: RES, 8.06 k, 1%, 0.1 W, 0603; Manufacturer: Vishay-Dale; CompType: Resistor; Value: 8.06k; Res_ohm: 8060; Value_Code: 8k06; Tolerance_%: 1; Power_W: 0.1; Value2: 0.1W; VDC_V: 75; TempCo: 100 ppm/C; SizeArea_mm2: 1.28; SizeX_mm: 1.6; SizeY_mm: 0.8; EIA_Code: E96; U/M: EA; AEC Category: Q200; Green_Lifecycle: Active; Green_REACh: Passed
R5 = CRCW06034K02FKEA: RES, 4.02 k, 1%, 0.1 W, 0603; Manufacturer: Vishay-Dale; CompType: Resistor; Value: 4.02k; Res_ohm: 4020; Value_Code: 4k02; Tolerance_%: 1; Power_W: 0.1; Value2: 0.1W; VDC_V: 75; TempCo: 100 ppm/C; SizeArea_mm2: 1.28; SizeX_mm: 1.6; SizeY_mm: 0.8; EIA_Code: E96; U/M: EA; AEC Category: Q200; Green_Lifecycle: Active; Green_REACh: Passed
R6 = CRCW2512100RJNEG: RES, 100, 5%, 1 W, AEC-Q200 Grade 0, 2512; Manufacturer: Vishay-Dale; CompType: Resistor; Value: 100; Value_Code: 100R; Tolerance_%: 5; Power_W: 1; VDC_V: 500; TempCo: 200 ppm/C; SizeArea_mm2: 20.16; SizeX_mm: 6.3; SizeY_mm: 3.2; SizeZ_mm: 0.71; EIA_Code: E24; U/M: EA; AEC Category: Q200; AEC Qualified: Y; AEC Grade: 0
R7 = CRCW060311K5FKEA: RES, 11.5 k, 1%, 0.1 W, 0603; Manufacturer: Vishay-Dale; CompType: Resistor; Value: 11.5k; Res_ohm: 11500; Value_Code: 11k5; Tolerance_%: 1; Power_W: 0.1; Value2: 0.1W; VDC_V: 75; TempCo: 100 ppm/C; SizeArea_mm2: 1.28; SizeX_mm: 1.6; SizeY_mm: 0.8; EIA_Code: E96; U/M: EA; AEC Category: Q200
R8 = MCT06030Z0000ZP500: RES, 0, 5%, 0.125 W, 0603; Manufacturer: Vishay/Beyschlag; CompType: Resistor; Value: 0; Value_Code: 0000; Tolerance_%: 5; Power_W: 0.125; Value2: 0.125W; TempCo: ppm/C; SizeArea_mm2: 1.28; SizeX_mm: 1.6; SizeY_mm: 0.8; SizeZ_mm: 1; EIA_Code: E24; U/M: EA; AEC Category: Q200; AEC Qualified: N; Green_Lifecycle: Active; Green_REACh: Passed
R9 = CRCW060310K0FKEA: RES, 10.0 k, 1%, 0.1 W, 0603; Manufacturer: Vishay-Dale; CompType: Resistor; Value: 10.0k; Res_ohm: 10000; Value_Code: 10k0; Tolerance_%: 1; Power_W: 0.1; Value2: 0.1W; VDC_V: 75; TempCo: 100 ppm/C; SizeArea_mm2: 1.28; SizeX_mm: 1.6; SizeY_mm: 0.8; EIA_Code: E96; U/M: EA; AEC Category: Q200
R10 R11 = CRM0805-FX-R910ELF: RES, 0.91, 1%, 0.25 W, 0805; Manufacturer: Bourns; CompType: Resistor; Value: 0.91; Value_Code: R910; Tolerance_%: 1; Power_W: 0.25; Value2: 0.25W; VDC_V: 0; TempCo: 100 ppm/C; EIA_Code: E96; U/M: EA; SizeArea_mm2: 2.5; SizeX_mm: 2; SizeY_mm: 1.25; SizeZ_mm: 1.45; AEC Category: Q200
R12 R15 = CRCW040224K9FKED: RES, 24.9 k, 1%, 0.063 W, 0402; Manufacturer: Vishay-Dale; CompType: Resistor; Value: 24.9k; Res_ohm: 24900; Value_Code: 24k9; Tolerance_%: 1; Power_W: 0.063; Value2: 0.063W; VDC_V: 50; TempCo: 100 ppm/C; SizeArea_mm2: 0.5; SizeZ_mm: 0.6; EIA_Code: E96; U/M: EA; AEC Category: Q200
R13 = ERJ-2RKF1001X: RES, 1.00 k, 1%, 0.1 W, 0402; Manufacturer: Panasonic; CompType: Resistor; Value: 1.00k; Res_ohm: 1000; Value_Code: 1k00; Tolerance_%: 1; Power_W: 0.1; Value2: 0.1W; VDC_V: 50; TempCo: 100 ppm/C; SizeArea_mm2: 0.5; SizeZ_mm: 0.6; EIA_Code: E96; U/M: EA; AEC Category: Q200; Green_Lifecycle: Active; Green_REACh: Passed
R14 = RMCF0402FT49R9: RES, 49.9, 1%, 0.063 W, AEC-Q200 Grade 0, 0402; Manufacturer: Stackpole Electronics Inc; CompType: Resistor; Value: 49.9; Value_Code: 49R9; Tolerance_%: 1; Power_W: 0.063; Value2: 0.063W; VDC_V: 50; TempCo: 100 ppm/C; SizeArea_mm2: 0.5; SizeZ_mm: 0.6; EIA_Code: E96; U/M: EA; AEC Category: Q200; AEC Qualified: Y; AEC Grade: 0
R16 = CRCW040247K0JNED: RES, 47 k, 5%, 0.063 W, 0402; Manufacturer: Vishay-Dale; CompType: Resistor; Value: 47k; Res_ohm: 47000; Value_Code: 47k0; Tolerance_%: 5; Power_W: 0.063; Value2: 0.063W; VDC_V: 50; TempCo: 200 ppm/C; SizeArea_mm2: 0.5; SizeX_mm: 1; SizeZ_mm: 0.6; EIA_Code: E24; U/M: EA; AEC Category: Q200
R17 = CRCW0603649RFKEA: RES, 649, 1%, 0.1 W, 0603; Manufacturer: Vishay-Dale; CompType: Resistor; Value: 649; Value_Code: 649R; Tolerance_%: 1; Power_W: 0.1; Value2: 0.1W; VDC_V: 75; TempCo: 100 ppm/C; SizeArea_mm2: 1.28; SizeX_mm: 1.6; SizeY_mm: 0.8; EIA_Code: E96; U/M: EA; AEC Category: Q200; Green_Lifecycle: Active; Green_REACh: Passed
R18 = CRCW04028K66FKED: RES, 8.66 k, 1%, 0.063 W, 0402; Manufacturer: Vishay-Dale; CompType: Resistor; Value: 8.66k; Res_ohm: 8660; Value_Code: 8k66; Tolerance_%: 1; Power_W: 0.063; Value2: 0.063W; VDC_V: 50; TempCo: 100 ppm/C; SizeArea_mm2: 0.5; SizeZ_mm: 0.6; EIA_Code: E96; U/M: EA; AEC Category: Q200
R19 = RC0402JR-070RL: RES, 0, 5%, 0.063 W, 0402; Manufacturer: Yageo America; CompType: Resistor; Value: 0; Value_Code: 0000; Tolerance_%: 5; Power_W: 0.063; Value2: 0.063W; VDC_V: 50; TempCo: 200 ppm/C; SizeArea_mm2: 0.5; SizeX_mm: 1; SizeZ_mm: 0.6; EIA_Code: E24; U/M: EA; AEC Category: Q200
R20 = CRCW060310K0FKEA: RES, 10.0 k, 1%, 0.1 W, 0603; Manufacturer: Vishay-Dale; CompType: Resistor; Value: 10.0k; Res_ohm: 10000; Value_Code: 10k0; Tolerance_%: 1; Power_W: 0.1; Value2: 0.1W; VDC_V: 75; TempCo: 100 ppm/C; SizeArea_mm2: 1.28; SizeX_mm: 1.6; SizeY_mm: 0.8; EIA_Code: E96; U/M: EA; AEC Category: Q200; Green_Lifecycle: Active; Green_REACh: Passed
R21 = CRCW04026K49FKED: RES, 6.49 k, 1%, 0.063 W, 0402; Manufacturer: Vishay-Dale; CompType: Resistor; Value: 6.49k; Res_ohm: 6490; Value_Code: 6k49; Tolerance_%: 1; Power_W: 0.063; Value2: 0.063W; VDC_V: 50; TempCo: 100 ppm/C; SizeArea_mm2: 0.5; SizeZ_mm: 0.6; EIA_Code: E96; U/M: EA; AEC Category: Q200; Green_Lifecycle: Active; Green_REACh: Passed
R22 = 3314J-1-101E: 3314 - 4 mm Square Trimpot Trimming Potentiometer; Manufacturer: Bourns; Sim Note: Enter the Resistance value and the set point into parameter fields.; SymbolCreator: a0412235; SizeAreaWB_mm2: 49; SizeArea_mm2: 25; SizeX_mm: 5; SizeZ_mm: 2.8
R23 R26 = CRCW040210R0JNED: RES, 10, 5%, 0.063 W, 0402; Manufacturer: Vishay-Dale; CompType: Resistor; Value: 10; Value_Code: 10R0; Tolerance_%: 5; Power_W: 0.063; Value2: 0.063W; VDC_V: 50; TempCo: 200 ppm/C; SizeArea_mm2: 0.5; SizeX_mm: 1; SizeZ_mm: 0.6; EIA_Code: E24; U/M: EA; AEC Category: Q200
R24 = CRCW0402237KFKED: RES, 237 k, 1%, 0.063 W, 0402; Manufacturer: Vishay-Dale; CompType: Resistor; Value: 237k; Res_ohm: 237000; Tolerance_%: 1; Power_W: 0.063; Value2: 0.063W; VDC_V: 50; TempCo: 100 ppm/C; SizeArea_mm2: 0.5; SizeZ_mm: 0.6; EIA_Code: E96; U/M: EA; AEC Category: Q200
R25 = 3314J-1-200E: 3314 - 4 mm Square Trimpot Trimming Potentiometer; Manufacturer: Bourns; Sim Note: Enter the Resistance value and the set point into parameter fields.; SymbolCreator: a0412235; SizeAreaWB_mm2: 49; SizeArea_mm2: 25; SizeX_mm: 5; SizeZ_mm: 2.8
R27 = CRCW06032K00JNEA: RES, 2.0 k, 5%, 0.1 W, 0603; Manufacturer: Vishay-Dale; CompType: Resistor; Value: 2.0k; Res_ohm: 2000; Value_Code: 2k00; Tolerance_%: 5; Power_W: 0.1; Value2: 0.1W; VDC_V: 75; TempCo: 200 ppm/C; SizeArea_mm2: 1.28; SizeX_mm: 1.6; SizeY_mm: 0.8; SizeZ_mm: 1; EIA_Code: E24; U/M: EA; AEC Category: Q200; Green_Lifecycle: Active; Green_REACh: Passed
R28 = CRCW040260K4FKED: RES, 60.4 k, 1%, 0.063 W, 0402; Manufacturer: Vishay-Dale; CompType: Resistor; Value: 60.4k; Res_ohm: 60400; Value_Code: 60k4; Tolerance_%: 1; Power_W: 0.063; Value2: 0.063W; VDC_V: 50; TempCo: 100 ppm/C; SizeArea_mm2: 0.5; SizeZ_mm: 0.6; EIA_Code: E96; U/M: EA; AEC Category: Q200
R29 = RC0603FR-07100KL: RES, 100 k, 1%, 0.1 W, 0603; Manufacturer: Yageo America; CompType: Resistor; Value: 100k; Res_ohm: 100000; Tolerance_%: 1; Power_W: 0.1; Value2: 0.1W; VDC_V: 150; TempCo: 200 ppm/C; SizeArea_mm2: 1.28; SizeX_mm: 1.6; SizeY_mm: 0.8; EIA_Code: E96; U/M: EA; AEC Category: Q200; Green_Lifecycle: Active; Green_REACh: Passed
R43 R128 = CRCW040268K1FKED: RES, 68.1 k, 1%, 0.063 W, 0402; Manufacturer: Vishay-Dale; CompType: Resistor; Value: 68.1k; Res_ohm: 68100; Value_Code: 68k1; Tolerance_%: 1; Power_W: 0.063; Value2: 0.063W; VDC_V: 50; TempCo: 100 ppm/C; SizeArea_mm2: 0.5; SizeZ_mm: 0.6; EIA_Code: E96; U/M: EA; AEC Category: Q200; Green_Lifecycle: Active; Green_REACh: Passed
R44 = CRCW040227K4FKED: RES, 27.4 k, 1%, 0.063 W, 0402; Manufacturer: Vishay-Dale; CompType: Resistor; Value: 27.4k; Res_ohm: 27400; Value_Code: 27k4; Tolerance_%: 1; Power_W: 0.063; Value2: 0.063W; VDC_V: 50; TempCo: 100 ppm/C; SizeArea_mm2: 0.5; SizeZ_mm: 0.6; EIA_Code: E96; U/M: EA; AEC Category: Q200; Green_Lifecycle: Not Set; Green_REACh: Incomplete
R125 R130 = CRCW04024K99FKED: RES, 4.99 k, 1%, 0.063 W, 0402; Manufacturer: Vishay-Dale; CompType: Resistor; Value: 4.99k; Res_ohm: 4990; Value_Code: 4k99; Tolerance_%: 1; Power_W: 0.063; Value2: 0.063W; VDC_V: 50; TempCo: 100 ppm/C; SizeArea_mm2: 0.5; SizeZ_mm: 0.6; EIA_Code: E96; U/M: EA; AEC Category: Q200; Green_Lifecycle: Active; Green_REACh: Passed
R126 R131 R132 = CRCW12060000Z0EA: RES, 0, 5%, 0.25 W, 1206; Manufacturer: Vishay-Dale; CompType: Resistor; Value: 0; Value_Code: 0000; Tolerance_%: 5; Power_W: 0.25; Value2: 0.25W; VDC_V: 200; TempCo: 200 ppm/C; SizeArea_mm2: 5.12; SizeX_mm: 3.2; SizeY_mm: 1.6; SizeZ_mm: 1.35; EIA_Code: E24; U/M: EA; AEC Category: Q200; Green_Lifecycle: Active; Green_REACh: Passed
R127 = CRCW060391K0JNEA: RES, 91 k, 5%, 0.1 W, 0603; Manufacturer: Vishay-Dale; CompType: Resistor; Value: 91k; Res_ohm: 91000; Value_Code: 91k0; Tolerance_%: 5; Power_W: 0.1; Value2: 0.1W; VDC_V: 75; TempCo: 200 ppm/C; SizeArea_mm2: 1.28; SizeX_mm: 1.6; SizeY_mm: 0.8; SizeZ_mm: 1; EIA_Code: E24; U/M: EA; AEC Category: Q200
R129 = CRCW04024K87FKED: RES, 4.87 k, 1%, 0.063 W, 0402; Manufacturer: Vishay-Dale; CompType: Resistor; Value: 4.87k; Res_ohm: 4870; Value_Code: 4k87; Tolerance_%: 1; Power_W: 0.063; Value2: 0.063W; VDC_V: 50; TempCo: 100 ppm/C; SizeArea_mm2: 0.5; SizeZ_mm: 0.6; EIA_Code: E96; U/M: EA; AEC Category: Q200; Green_Lifecycle: Active; Green_REACh: Passed
T1 = LDT0937-50: Transformer, 150 uH, SMT; Manufacturer: Linkcom Manufacturing Co.; SymbolCreator: Altium; ValueDisplayed: 150µH; Value: 150uH; Lp: 150; DCR_ohm: 0.38; Ns1toNp: 0.389; SizeAreaWB_mm2: 312; SizeArea_mm2: 245; SizeX_mm: 14; SizeY_mm: 17.5; Ind_H: 0.00015; LeakageInd_H: 1.5E-6; Rsec1_ohm: 0.043
U1 = TPS23755RJJ: IEEE 802.3at PoE PD with No-Opto Flyback DC-DC Controller, RJJ0023B (VQFN-23); Manufacturer: Texas Instruments; SymbolCreator: a0411947; SizeArea_mm2: 24; SizeAreaWB_mm2: 48; SizeX_mm: 4; SizeY_mm: 6; SizeZ_mm: 1; CompType: IC; U/M: EA
U2 = CMP-0078351-3: 2.7V-22V, 4A, 50mohm Priority Power MUX, RUX0012A (VQFN-HR-12); Alternate PartNumber: TPS2121RUXT; Alternate Manufacturer: Texas Instruments; SizeAreaWB_mm2: 10.5; SizeZ_mm: 1; SizeX_mm: 2; SizeY_mm: 2.5; SizeArea_mm2: 5; CompType: IC; AEC Qualified: N; AEC Category: Q200
U3 = HMHA2801A: Optocoupler, 3.75 kV, 80-160% CTR, SMT; Manufacturer: Fairchild Semiconductor; CTR (Min): 80%; CTR (Max): 160%; Voltage_Isolation_Vrms: 3750V; SizeAreaWB_mm2: 4; SizeArea_mm2: 1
